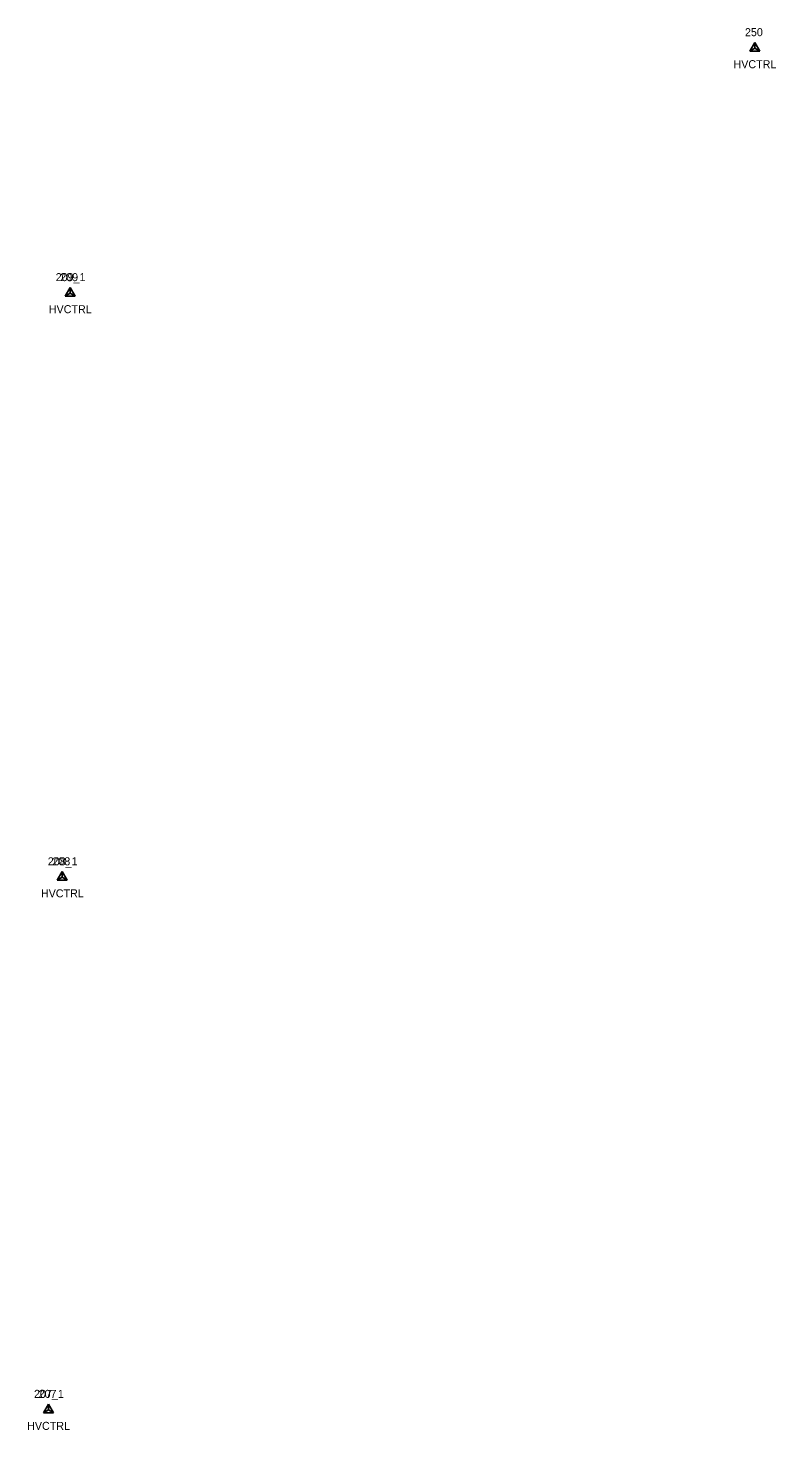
# Model space of a CAD drawing. Extents: x 1769141 to 1770817, y 735471 to 742405.
# Drawn here: x 1770294.9 to 1770481.8, y 737809.4 to 738159.7 of the extents above; entities that cross this region are included whole.
import ezdxf

# ---------------------------------------------------------------- set-up
doc = ezdxf.new("R2010")
doc.units = 0
for name, color, linetype in [('C_A', 7, 'Continuous'), ('C_I', 7, 'Continuous'), ('CPSM', 7, 'Continuous')]:
    doc.layers.add(name, color=color, linetype=linetype)

msp = doc.modelspace()

# ---------------------------------------------------------------- linework, layer by layer
at = {"layer": 'CPSM'}
for p, q in [((1770475.27, 738153.96), (1770476.52, 738156.13)), ((1770475.27, 738153.96), (1770476.52, 738154.68)), ((1770477.77, 738153.96), (1770476.52, 738156.13)), ((1770476.52, 738154.68), (1770476.52, 738156.13)), ((1770476.52, 738154.68), (1770476.52, 738154.68)), ((1770476.52, 738154.68), (1770477.77, 738153.96)), ((1770475.27, 738153.96), (1770477.77, 738153.96)), ((1770304.17, 738092.75), (1770305.42, 738094.91)), ((1770304.17, 738092.75), (1770305.42, 738094.91)), ((1770304.17, 738092.75), (1770305.42, 738093.47)), ((1770304.17, 738092.75), (1770305.42, 738093.47)), ((1770304.17, 738092.75), (1770306.67, 738092.75)), ((1770304.17, 738092.75), (1770306.67, 738092.75)), ((1770306.67, 738092.75), (1770305.42, 738094.91)), ((1770305.42, 738093.47), (1770305.42, 738094.91)), ((1770306.67, 738092.75), (1770305.42, 738094.91)), ((1770305.42, 738093.47), (1770305.42, 738094.91)), ((1770305.42, 738093.47), (1770305.42, 738093.47)), ((1770305.42, 738093.47), (1770306.67, 738092.75)), ((1770305.42, 738093.47), (1770305.42, 738093.47)), ((1770305.42, 738093.47), (1770306.67, 738092.75)), ((1770302.2, 737946.8), (1770303.45, 737948.96)), ((1770302.2, 737946.8), (1770303.45, 737948.96)), ((1770304.7, 737946.8), (1770303.45, 737948.96)), ((1770303.46, 737947.52), (1770303.45, 737948.96)), ((1770304.7, 737946.8), (1770303.45, 737948.96)), ((1770303.46, 737947.52), (1770303.45, 737948.96)), ((1770302.2, 737946.8), (1770303.46, 737947.52)), ((1770302.2, 737946.8), (1770303.46, 737947.52)), ((1770302.2, 737946.8), (1770304.7, 737946.8)), ((1770302.2, 737946.8), (1770304.7, 737946.8)), ((1770303.46, 737947.52), (1770303.46, 737947.52)), ((1770303.46, 737947.52), (1770304.7, 737946.8)), ((1770303.46, 737947.52), (1770303.46, 737947.52)), ((1770303.46, 737947.52), (1770304.7, 737946.8)), ((1770298.76, 737813.75), (1770300.01, 737815.92)), ((1770298.76, 737813.75), (1770300.01, 737815.92)), ((1770301.26, 737813.75), (1770300.01, 737815.92)), ((1770300.01, 737814.47), (1770300.01, 737815.92)), ((1770301.26, 737813.75), (1770300.01, 737815.92)), ((1770300.01, 737814.47), (1770300.01, 737815.92)), ((1770298.76, 737813.75), (1770300.01, 737814.47)), ((1770298.76, 737813.75), (1770300.01, 737814.47)), ((1770298.76, 737813.75), (1770301.26, 737813.75)), ((1770298.76, 737813.75), (1770301.26, 737813.75)), ((1770300.01, 737814.47), (1770300.01, 737814.47)), ((1770300.01, 737814.47), (1770301.26, 737813.75)), ((1770300.01, 737814.47), (1770300.01, 737814.47)), ((1770300.01, 737814.47), (1770301.26, 737813.75))]:
    msp.add_line(p, q, dxfattribs=at)

# ---------------------------------------------------------------- texts
at = {"layer": 'C_A'}
for p in [(1770471.22, 738149.68), (1770300.12, 738088.47), (1770300.12, 738088.47), (1770298.15, 737942.52), (1770298.15, 737942.52), (1770294.7, 737809.47), (1770294.7, 737809.47)]:
    msp.add_text('HVCTRL', height=2, dxfattribs=at).set_placement(p)
at = {"layer": 'C_I'}
for s, p in [('250', (1770474.08, 738157.68)), ('209_1', (1770301.83, 738096.47)), ('209', (1770302.97, 738096.47)), ('208_1', (1770299.86, 737950.52)), ('208', (1770301.01, 737950.52)), ('207_1', (1770296.42, 737817.47)), ('207', (1770297.57, 737817.47))]:
    msp.add_text(s, height=2, dxfattribs=at).set_placement(p)

doc.saveas('drawing.dxf')
